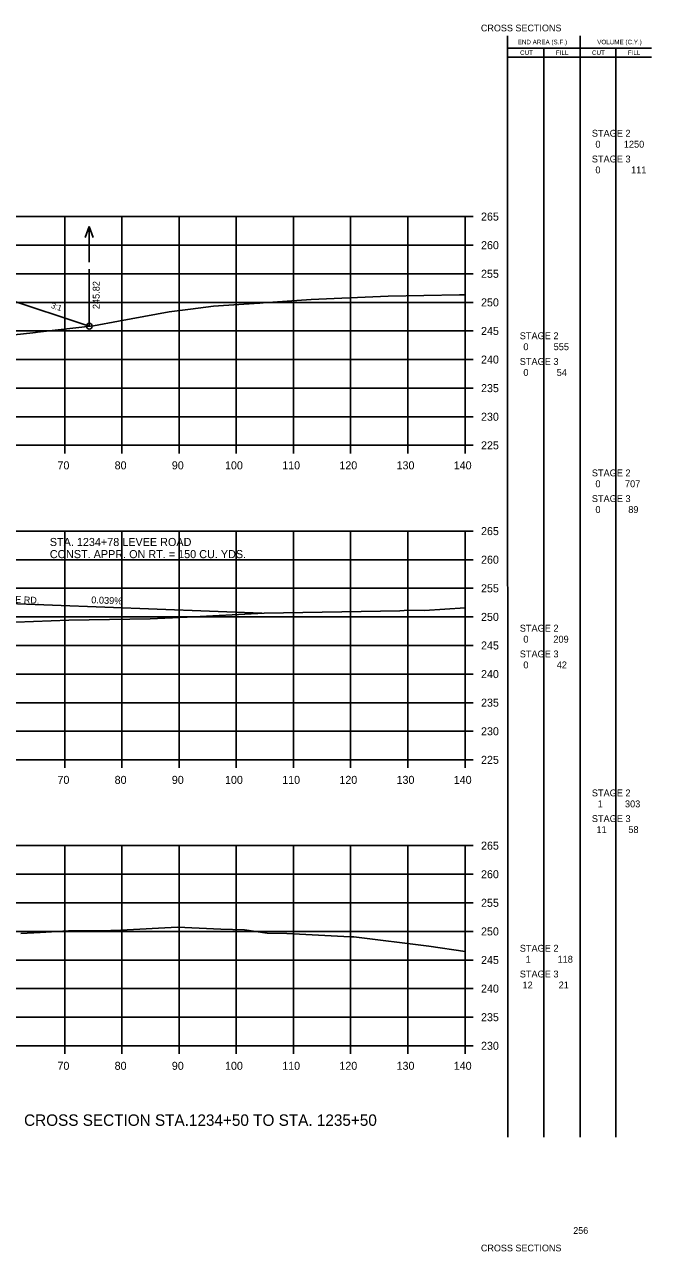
# Model space of a CAD drawing. Extents: x 1342547 to 1344156, y -1532351 to -1517216.
# Drawn here: x 1342765.8 to 1342875.5, y -1529593.7 to -1529379.2 of the extents above; entities that cross this region are included whole.
import ezdxf

# ---------------------------------------------------------------- set-up
doc = ezdxf.new("R2010")
doc.units = 0
for name, color, linetype in [('Level 2', 7, 'Continuous'), ('R_Axis', 7, 'Continuous'), ('R_Axis Annot', 7, 'Continuous'), ('R_Border Notes', 7, 'Continuous'), ('R_Draft', 7, 'Continuous'), ('R_Drive', 7, 'Continuous'), ('R_Exist Surface', 7, 'Continuous'), ('R_Fin Surface', 7, 'Continuous'), ('R_Grid', 7, 'Continuous'), ('R_No Plot', 7, 'Continuous'), ('R_Water', 7, 'Continuous'), ('R_Xsect Elev', 7, 'Continuous'), ('R_Xsect Slope', 7, 'Continuous')]:
    doc.layers.add(name, color=color, linetype=linetype)

msp = doc.modelspace()

# ---------------------------------------------------------------- linework, layer by layer
at = {"layer": 'Level 2'}
for p, q in [((1342850.33, -1529573.76), (1342850.32, -1529381.15)), ((1342862.99, -1529573.76), (1342862.99, -1529381.15)), ((1342850.32, -1529383.31), (1342863.59, -1529383.31)), ((1342856.66, -1529573.76), (1342856.66, -1529383.31)), ((1342863.59, -1529383.31), (1342875.48, -1529383.31)), ((1342869.23, -1529573.76), (1342869.23, -1529383.31)), ((1342850.32, -1529384.87), (1342863.59, -1529384.87)), ((1342863.59, -1529384.87), (1342875.48, -1529384.87))]:
    msp.add_line(p, q, dxfattribs=at)
at = {"layer": 'R_Axis'}
for p, q in [((1342842.87, -1529452.76), (1342842.87, -1529412.76)), ((1342844.27, -1529412.76), (1342842.87, -1529412.76)), ((1342844.27, -1529417.76), (1342842.87, -1529417.76)), ((1342844.27, -1529422.76), (1342842.87, -1529422.76)), ((1342844.27, -1529427.76), (1342842.87, -1529427.76)), ((1342844.27, -1529432.76), (1342842.87, -1529432.76)), ((1342844.27, -1529437.76), (1342842.87, -1529437.76)), ((1342844.27, -1529442.76), (1342842.87, -1529442.76)), ((1342844.27, -1529447.76), (1342842.87, -1529447.76)), ((1342562.87, -1529452.76), (1342842.87, -1529452.76)), ((1342772.87, -1529454.16), (1342772.87, -1529452.76)), ((1342782.87, -1529454.16), (1342782.87, -1529452.76)), ((1342792.87, -1529454.16), (1342792.87, -1529452.76)), ((1342802.87, -1529454.16), (1342802.87, -1529452.76)), ((1342812.87, -1529454.16), (1342812.87, -1529452.76)), ((1342822.87, -1529454.16), (1342822.87, -1529452.76)), ((1342832.87, -1529454.16), (1342832.87, -1529452.76)), ((1342842.87, -1529454.16), (1342842.87, -1529452.76)), ((1342844.27, -1529452.76), (1342842.87, -1529452.76)), ((1342842.87, -1529507.76), (1342842.87, -1529467.76)), ((1342844.27, -1529467.76), (1342842.87, -1529467.76)), ((1342844.27, -1529472.76), (1342842.87, -1529472.76)), ((1342844.27, -1529477.76), (1342842.87, -1529477.76)), ((1342844.27, -1529482.76), (1342842.87, -1529482.76)), ((1342844.27, -1529487.76), (1342842.87, -1529487.76)), ((1342844.27, -1529492.76), (1342842.87, -1529492.76)), ((1342844.27, -1529497.76), (1342842.87, -1529497.76)), ((1342844.27, -1529502.76), (1342842.87, -1529502.76)), ((1342562.87, -1529507.76), (1342842.87, -1529507.76)), ((1342772.87, -1529509.16), (1342772.87, -1529507.76)), ((1342782.87, -1529509.16), (1342782.87, -1529507.76)), ((1342792.87, -1529509.16), (1342792.87, -1529507.76)), ((1342802.87, -1529509.16), (1342802.87, -1529507.76)), ((1342812.87, -1529509.16), (1342812.87, -1529507.76)), ((1342822.87, -1529509.16), (1342822.87, -1529507.76)), ((1342832.87, -1529509.16), (1342832.87, -1529507.76)), ((1342842.87, -1529509.16), (1342842.87, -1529507.76)), ((1342844.27, -1529507.76), (1342842.87, -1529507.76)), ((1342842.87, -1529557.76), (1342842.87, -1529522.76)), ((1342844.27, -1529522.76), (1342842.87, -1529522.76)), ((1342844.27, -1529527.76), (1342842.87, -1529527.76)), ((1342844.27, -1529532.76), (1342842.87, -1529532.76)), ((1342844.27, -1529537.76), (1342842.87, -1529537.76)), ((1342844.27, -1529542.76), (1342842.87, -1529542.76)), ((1342844.27, -1529547.76), (1342842.87, -1529547.76)), ((1342844.27, -1529552.76), (1342842.87, -1529552.76)), ((1342562.87, -1529557.76), (1342842.87, -1529557.76)), ((1342772.87, -1529559.16), (1342772.87, -1529557.76)), ((1342782.87, -1529559.16), (1342782.87, -1529557.76)), ((1342792.87, -1529559.16), (1342792.87, -1529557.76)), ((1342802.87, -1529559.16), (1342802.87, -1529557.76)), ((1342812.87, -1529559.16), (1342812.87, -1529557.76)), ((1342822.87, -1529559.16), (1342822.87, -1529557.76)), ((1342832.87, -1529559.16), (1342832.87, -1529557.76)), ((1342842.87, -1529559.16), (1342842.87, -1529557.76)), ((1342844.27, -1529557.76), (1342842.87, -1529557.76))]:
    msp.add_line(p, q, dxfattribs=at)
at = {"layer": 'R_Drive'}
msp.add_lwpolyline([(1342734.37, -1529480.07), (1342752.36, -1529480), (1342807.36, -1529482.13)], dxfattribs=at)
at = {"layer": 'R_Exist Surface'}
for points in [[(1342746.07, -1529435.37), (1342767.27, -1529433.1), (1342767.78, -1529433.02), (1342768.01, -1529432.99), (1342768.11, -1529432.98), (1342777.91, -1529431.85), (1342782.3, -1529431.02), (1342791.14, -1529429.42), (1342794.89, -1529428.97), (1342798.9, -1529428.41), (1342806.86, -1529427.9), (1342806.96, -1529427.88), (1342807.03, -1529427.87), (1342807.57, -1529427.82), (1342815.95, -1529427.26), (1342829.45, -1529426.66), (1342841.89, -1529426.43), (1342842.87, -1529426.43)], [(1342764.34, -1529483.66), (1342773.59, -1529483.34), (1342787.82, -1529483.12), (1342794.3, -1529482.79), (1342807.77, -1529482.11), (1342831.46, -1529481.72), (1342832.96, -1529481.56), (1342835.78, -1529481.62), (1342842.87, -1529481.16)], [(1342765.2, -1529538.13), (1342768.55, -1529537.93), (1342773.54, -1529537.66), (1342780.95, -1529537.61), (1342782.68, -1529537.52), (1342792.59, -1529537.03), (1342792.6, -1529537.03), (1342800.19, -1529537.35), (1342804.32, -1529537.51), (1342808.28, -1529538.05), (1342811.7, -1529538.1), (1342822.8, -1529538.68), (1342823.15, -1529538.7), (1342823.43, -1529538.73), (1342836.54, -1529540.34), (1342842.87, -1529541.29)]]:
    msp.add_lwpolyline(points, dxfattribs=at)
at = {"layer": 'R_Fin Surface'}
msp.add_lwpolyline([(1342638.21, -1529434.07), (1342643.37, -1529432.35), (1342653.42, -1529430.67), (1342665.37, -1529428.68), (1342671.37, -1529428.35), (1342673.37, -1529428.24), (1342702.87, -1529426.62), (1342732.37, -1529425), (1342734.37, -1529424.89), (1342745.87, -1529424.25), (1342762.37, -1529427), (1342777.17, -1529431.94)], dxfattribs=at)
at = {"layer": 'R_Grid'}
for p, q in [((1342562.87, -1529412.76), (1342842.87, -1529412.76)), ((1342772.87, -1529452.76), (1342772.87, -1529412.76)), ((1342782.87, -1529452.76), (1342782.87, -1529412.76)), ((1342792.87, -1529452.76), (1342792.87, -1529412.76)), ((1342802.87, -1529452.76), (1342802.87, -1529412.76)), ((1342812.87, -1529452.76), (1342812.87, -1529412.76)), ((1342822.87, -1529452.76), (1342822.87, -1529412.76)), ((1342832.87, -1529452.76), (1342832.87, -1529412.76)), ((1342842.87, -1529452.76), (1342842.87, -1529412.76)), ((1342562.87, -1529417.76), (1342842.87, -1529417.76)), ((1342562.87, -1529422.76), (1342842.87, -1529422.76)), ((1342562.87, -1529427.76), (1342842.87, -1529427.76)), ((1342562.87, -1529432.76), (1342842.87, -1529432.76)), ((1342562.87, -1529437.76), (1342842.87, -1529437.76)), ((1342562.87, -1529442.76), (1342842.87, -1529442.76)), ((1342562.87, -1529447.76), (1342842.87, -1529447.76)), ((1342562.87, -1529452.76), (1342842.87, -1529452.76)), ((1342562.87, -1529467.76), (1342842.87, -1529467.76)), ((1342772.87, -1529507.76), (1342772.87, -1529467.76)), ((1342782.87, -1529507.76), (1342782.87, -1529467.76)), ((1342792.87, -1529507.76), (1342792.87, -1529467.76)), ((1342802.87, -1529507.76), (1342802.87, -1529467.76)), ((1342812.87, -1529507.76), (1342812.87, -1529467.76)), ((1342822.87, -1529507.76), (1342822.87, -1529467.76)), ((1342832.87, -1529507.76), (1342832.87, -1529467.76)), ((1342842.87, -1529507.76), (1342842.87, -1529467.76)), ((1342562.87, -1529472.76), (1342842.87, -1529472.76)), ((1342562.87, -1529477.76), (1342842.87, -1529477.76)), ((1342562.87, -1529482.76), (1342842.87, -1529482.76)), ((1342562.87, -1529487.76), (1342842.87, -1529487.76)), ((1342562.87, -1529492.76), (1342842.87, -1529492.76)), ((1342562.87, -1529497.76), (1342842.87, -1529497.76)), ((1342562.87, -1529502.76), (1342842.87, -1529502.76)), ((1342562.87, -1529507.76), (1342842.87, -1529507.76)), ((1342562.87, -1529522.76), (1342842.87, -1529522.76)), ((1342772.87, -1529557.76), (1342772.87, -1529522.76)), ((1342782.87, -1529557.76), (1342782.87, -1529522.76)), ((1342792.87, -1529557.76), (1342792.87, -1529522.76)), ((1342802.87, -1529557.76), (1342802.87, -1529522.76)), ((1342812.87, -1529557.76), (1342812.87, -1529522.76)), ((1342822.87, -1529557.76), (1342822.87, -1529522.76)), ((1342832.87, -1529557.76), (1342832.87, -1529522.76)), ((1342842.87, -1529557.76), (1342842.87, -1529522.76)), ((1342562.87, -1529527.76), (1342842.87, -1529527.76)), ((1342562.87, -1529532.76), (1342842.87, -1529532.76)), ((1342562.87, -1529537.76), (1342842.87, -1529537.76)), ((1342562.87, -1529542.76), (1342842.87, -1529542.76)), ((1342562.87, -1529547.76), (1342842.87, -1529547.76)), ((1342562.87, -1529552.76), (1342842.87, -1529552.76)), ((1342562.87, -1529557.76), (1342842.87, -1529557.76))]:
    msp.add_line(p, q, dxfattribs=at)
at = {"layer": 'R_No Plot'}
msp.add_circle((1342777.17, -1529431.94), 0.5, dxfattribs=at)
at = {"layer": 'R_Water'}
for p, q in [((1342777.12, -1529414.47), (1342776.42, -1529416.39)), ((1342777.12, -1529420.75), (1342777.12, -1529414.47)), ((1342777.12, -1529414.47), (1342777.82, -1529416.39))]:
    msp.add_line(p, q, dxfattribs=at)
at = {"layer": 'R_Xsect Elev'}
msp.add_line((1342777.17, -1529431.94), (1342777.17, -1529421.94), dxfattribs=at)

# ---------------------------------------------------------------- texts
at = {"layer": 'Level 2'}
for s, height, p in [('END AREA (S.F.)', 0.7937, (1342852.08, -1529382.63)), ('CUT', 0.794, (1342852.5, -1529384.49)), ('FILL', 0.794, (1342858.76, -1529384.49)), ('CUT', 0.794, (1342865.07, -1529384.49)), ('VOLUME (C.Y.)', 0.7937, (1342865.99, -1529382.63)), ('FILL', 0.794, (1342871.33, -1529384.49)), (' STAGE 2 ', 1.2, (1342864.6, -1529398.79)), ('0', 1.2, (1342865.67, -1529400.7)), ('1250', 1.2, (1342870.64, -1529400.7)), (' STAGE 3 ', 1.2, (1342864.6, -1529403.29)), ('0', 1.2, (1342865.67, -1529405.2)), ('111', 1.2, (1342871.91, -1529405.2)), (' STAGE 2 ', 1.2, (1342852, -1529434.2)), ('0', 1.2, (1342853.07, -1529436.12)), ('555', 1.2, (1342858.37, -1529436.12)), (' STAGE 3 ', 1.2, (1342852, -1529438.7)), ('0', 1.2, (1342853.07, -1529440.62)), ('54', 1.2, (1342858.91, -1529440.62)), (' STAGE 2 ', 1.2, (1342864.6, -1529458.18)), ('0', 1.2, (1342865.67, -1529460.09)), ('707', 1.2, (1342870.84, -1529460.09)), (' STAGE 3 ', 1.2, (1342864.6, -1529462.68)), ('0', 1.2, (1342865.67, -1529464.59)), ('89', 1.2, (1342871.42, -1529464.59)), (' STAGE 2 ', 1.2, (1342852, -1529485.34)), ('0', 1.2, (1342853.07, -1529487.26)), ('209', 1.2, (1342858.32, -1529487.26)), (' STAGE 3 ', 1.2, (1342852, -1529489.84)), ('0', 1.2, (1342853.07, -1529491.76)), ('42', 1.2, (1342858.91, -1529491.76)), (' STAGE 2 ', 1.2, (1342864.6, -1529514.14)), ('1', 1.2, (1342866.06, -1529516.06)), ('303', 1.2, (1342870.84, -1529516.06)), (' STAGE 3 ', 1.2, (1342864.6, -1529518.64)), ('11', 1.2, (1342865.86, -1529520.56)), ('58', 1.2, (1342871.43, -1529520.56)), (' STAGE 2 ', 1.2, (1342852, -1529541.31)), ('1', 1.2, (1342853.46, -1529543.23)), ('118', 1.2, (1342859.05, -1529543.23)), (' STAGE 3 ', 1.2, (1342852, -1529545.81)), ('12', 1.2, (1342852.92, -1529547.73)), ('21', 1.2, (1342859.25, -1529547.73))]:
    msp.add_text(s, height=height, dxfattribs=at).set_placement(p)
at = {"layer": 'R_Axis Annot'}
for s, p in [('265', (1342845.67, -1529413.46)), ('260', (1342845.67, -1529418.46)), ('255', (1342845.67, -1529423.46)), ('250', (1342845.67, -1529428.46)), ('245', (1342845.67, -1529433.46)), ('240', (1342845.67, -1529438.46)), ('235', (1342845.67, -1529443.46)), ('230', (1342845.67, -1529448.46)), ('225', (1342845.67, -1529453.46)), ('70', (1342771.6, -1529456.96)), ('80', (1342781.6, -1529456.96)), ('90', (1342791.6, -1529456.96)), ('100', (1342800.9, -1529456.96)), ('110', (1342810.9, -1529456.96)), ('120', (1342820.9, -1529456.96)), ('130', (1342830.9, -1529456.96)), ('140', (1342840.9, -1529456.96)), ('265', (1342845.67, -1529468.46)), ('260', (1342845.67, -1529473.46)), ('255', (1342845.67, -1529478.46)), ('250', (1342845.67, -1529483.46)), ('245', (1342845.67, -1529488.46)), ('240', (1342845.67, -1529493.46)), ('235', (1342845.67, -1529498.46)), ('230', (1342845.67, -1529503.46)), ('225', (1342845.67, -1529508.46)), ('70', (1342771.6, -1529511.96)), ('80', (1342781.6, -1529511.96)), ('90', (1342791.6, -1529511.96)), ('100', (1342800.9, -1529511.96)), ('110', (1342810.9, -1529511.96)), ('120', (1342820.9, -1529511.96)), ('130', (1342830.9, -1529511.96)), ('140', (1342840.9, -1529511.96)), ('265', (1342845.67, -1529523.46)), ('260', (1342845.67, -1529528.46)), ('255', (1342845.67, -1529533.46)), ('250', (1342845.67, -1529538.46)), ('245', (1342845.67, -1529543.46)), ('240', (1342845.67, -1529548.46)), ('235', (1342845.67, -1529553.46)), ('230', (1342845.67, -1529558.46)), ('70', (1342771.6, -1529561.96)), ('80', (1342781.6, -1529561.96)), ('90', (1342791.6, -1529561.96)), ('100', (1342800.9, -1529561.96)), ('110', (1342810.9, -1529561.96)), ('120', (1342820.9, -1529561.96)), ('130', (1342830.9, -1529561.96)), ('140', (1342840.9, -1529561.96))]:
    msp.add_text(s, height=1.4, dxfattribs=at).set_placement(p)
at = {"layer": 'R_Border Notes'}
for s, height, p in [('CROSS SECTIONS', 1.1775, (1342845.65, -1529380.37)), ('STA. 1234+78 LEVEE ROAD', 1.4147, (1342770.26, -1529470.37)), ('STA. 1234+78 LEVEE ROAD', 1.4147, (1342770.26, -1529470.37)), ('CONST. APPR. ON RT. = 150 CU. YDS.', 1.4147, (1342770.26, -1529472.49)), ('CONST. APPR. ON RT. = 150 CU. YDS.', 1.4147, (1342770.26, -1529472.49)), ('256', 1.178, (1342861.79, -1529590.65)), ('CROSS SECTIONS', 1.1775, (1342845.65, -1529593.71))]:
    msp.add_text(s, height=height, dxfattribs=at).set_placement(p)
msp.add_text('LEVEE RD.', height=1.178, rotation=357.8604, dxfattribs=at).set_placement((1342760.18, -1529480.15))
at = {"layer": 'R_Draft'}
msp.add_text('CROSS SECTION STA.1234+50 TO STA. 1235+50', height=2, dxfattribs=at).set_placement((1342765.76, -1529571.76))
at = {"layer": 'R_Xsect Elev'}
for s, rotation, p in [('245.82', 90, (1342778.97, -1529428.94)), ('0.039%', 357.7871, (1342777.49, -1529480.37))]:
    msp.add_text(s, height=1.2, rotation=rotation, dxfattribs=at).set_placement(p)
at = {"layer": 'R_Xsect Slope'}
msp.add_text('3:1', height=1, rotation=341.5651, dxfattribs=at).set_placement((1342770.4, -1529428.71))

doc.saveas('drawing.dxf')
